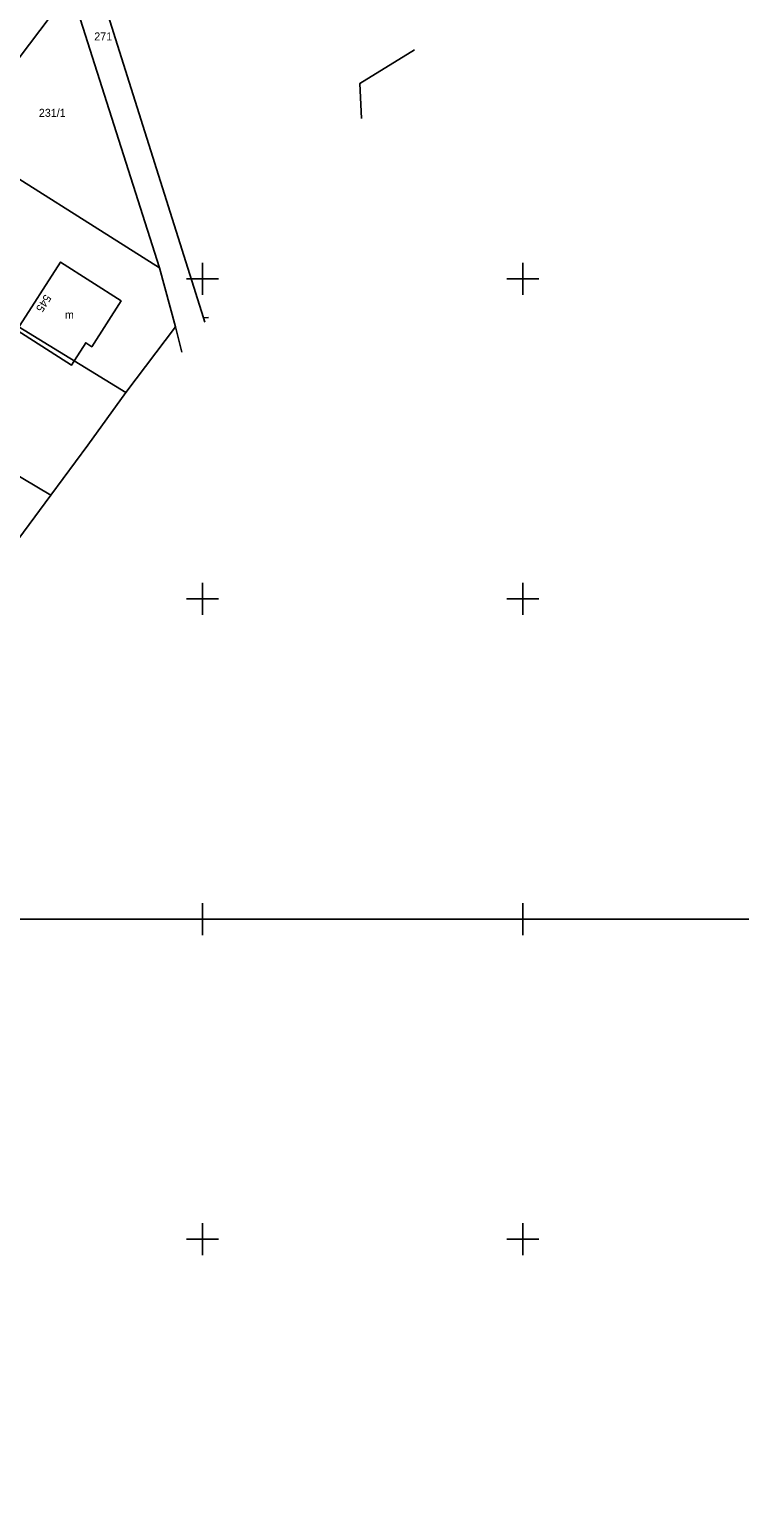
# Model space of a CAD drawing. Extents: x 4632591 to 4653165, y 5351032 to 5369868.
# Drawn here: x 4647673 to 4647783.8, y 5363658.3 to 5363888.9 of the extents above; entities that cross this region are included whole.
import ezdxf

# ---------------------------------------------------------------- set-up
doc = ezdxf.new("R2010")
doc.units = 0
for name, color, linetype in [('EADPD_238', 7, 'Continuous'), ('EBUPP_316', 7, 'Continuous'), ('EDZPD_211', 7, 'Continuous'), ('EDZPD_219', 7, 'Continuous'), ('Warstwa 60', 7, 'Continuous')]:
    doc.layers.add(name, color=color, linetype=linetype)

msp = doc.modelspace()

# ---------------------------------------------------------------- linework, layer by layer
at = {"layer": 'EBUPP_316'}
msp.add_lwpolyline([(4647671.01, 5363841.95), (4647677.84, 5363852.6), (4647687.28, 5363846.54), (4647682.69, 5363839.39), (4647681.75, 5363840), (4647679.51, 5363836.5)], close=True, dxfattribs=at)
at = {"layer": 'EDZPD_219'}
msp.add_line((4647700.17, 5363843.9), (4647700.92, 5363843.95), dxfattribs=at)
for points in [[(4647682.76, 5363899.1), (4647700.17, 5363843.9)], [(4647661.64, 5363871.71), (4647679.44, 5363895.24)], [(4647679.44, 5363895.24), (4647693.29, 5363851.7)], [(4647724.83, 5363875.03), (4647724.56, 5363880.52), (4647733.07, 5363885.75)], [(4647661.64, 5363871.71), (4647693.29, 5363851.7)], [(4647649.75, 5363855.69), (4647688.03, 5363832.26)], [(4647693.29, 5363851.7), (4647695.77, 5363842.52)], [(4647688.03, 5363832.26), (4647695.77, 5363842.52)], [(4647695.77, 5363842.52), (4647696.77, 5363838.56)], [(4647700.17, 5363843.9), (4647700.92, 5363843.95)], [(4647700.17, 5363843.9), (4647700.35, 5363843.2)], [(4647637.15, 5363839.47), (4647676.31, 5363816.21)], [(4647682.1, 5363824.02), (4647688.03, 5363832.26)], [(4647676.31, 5363816.21), (4647682.1, 5363824.02)], [(4647664.34, 5363800.05), (4647676.31, 5363816.21)]]:
    msp.add_lwpolyline(points, dxfattribs=at)
at = {"layer": 'Warstwa 60'}
for p, q in [((4647700, 5363847.5), (4647700, 5363852.5)), ((4647750, 5363847.5), (4647750, 5363852.5)), ((4647697.5, 5363850), (4647702.5, 5363850)), ((4647747.5, 5363850), (4647752.5, 5363850)), ((4647700, 5363797.5), (4647700, 5363802.5)), ((4647750, 5363797.5), (4647750, 5363802.5)), ((4647697.5, 5363800), (4647702.5, 5363800)), ((4647747.5, 5363800), (4647752.5, 5363800)), ((4647700, 5363750), (4647700, 5363752.5)), ((4647750, 5363750), (4647750, 5363752.5)), ((4647700, 5363747.5), (4647700, 5363750)), ((4647750, 5363747.5), (4647750, 5363750)), ((4647700, 5363697.5), (4647700, 5363702.5)), ((4647750, 5363697.5), (4647750, 5363702.5)), ((4647697.5, 5363700), (4647702.5, 5363700)), ((4647747.5, 5363700), (4647752.5, 5363700))]:
    msp.add_line(p, q, dxfattribs=at)
for points in [[(4647600, 5363750), (4647600, 5364000), (4648000, 5364000), (4648000, 5363750)], [(4647600, 5363500), (4647600, 5363750), (4648000, 5363750), (4648000, 5363500)]]:
    msp.add_lwpolyline(points, close=True, dxfattribs=at)

# ---------------------------------------------------------------- texts
at = {"layer": 'EADPD_238'}
msp.add_text('545', height=1.25, rotation=237.2996, dxfattribs=at).set_placement((4647675.42, 5363847.67))
at = {"layer": 'EBUPP_316'}
msp.add_text('m', height=1.25, dxfattribs=at).set_placement((4647678.51, 5363843.76))
at = {"layer": 'EDZPD_211'}
for s, p in [('271', (4647683.09, 5363887.22)), ('231/1', (4647674.44, 5363875.29))]:
    msp.add_text(s, height=1.25, dxfattribs=at).set_placement(p)

doc.saveas('drawing.dxf')
